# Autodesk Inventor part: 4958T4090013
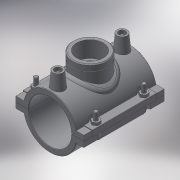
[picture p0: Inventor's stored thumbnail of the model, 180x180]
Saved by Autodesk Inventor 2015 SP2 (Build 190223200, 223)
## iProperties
Created: 2017-07
Part Number: 4958T4090013
Material: Generic
Description: PLASSON SADDLE 90X1.1/4" FEMALE BSPP
Document SubType Name: Modeling
Designer: KIM
Density: 1 g/cm^3
Appearance: Default
Author: KIM
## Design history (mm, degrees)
derived "4958T4.ipt"
feature "Solid1::4958T4.ipt"
tag "TaggingFeature1"
body "Solid1"
other parameters: "d1" = 112.5, "d2" = 126, "d3" = 22.5, "d4" = 118, "d5" = 0, "d6" = 0.1, "d8" = 0, "d19" = 6, "d20" = 6, "d21" = 70.8, "d23" = 0, "d24" = 35.4, "d26" = 0, "d27" = 3, "d28" = 3, "d29" = 3, "d30" = 24.00694, "d31" = 6, "d32" = 0, "d33" = 0, "d34" = 0.6, "d40" = 60.3, "d43" = 0, "d45" = 0, "d46" = 9, "d47" = 75, "d48" = 50.6376, "d50" = 0, "d51" = 38.952, "d52" = 24, "d53" = 0, "d54" = 31.1616, "d56" = 0, "d57" = -9, "d58" = 0.5, "d59" = 0.1, "d60" = 0, "d61" = 0.5, "d64" = 1.16856, "d67" = 0.9, "d70" = 15, "d72" = 0, "d73" = 6, "d75" = 5, "d76" = 0, "d77" = 4.5, "d78" = 74, "d79" = 15, "d80" = 47.2, "d82" = 5 deg, "d84" = 4, "d85" = 14, "d86" = 0, "d87" = 3, "d88" = 0, "d89" = 1, "d90" = 1, "d91" = 94.4, "d92" = 0, "d93" = 0.5, "d94" = 47.36842, "Rp_" = 38.952, "B_" = 126, "L_" = 118, "d_t" = 6
